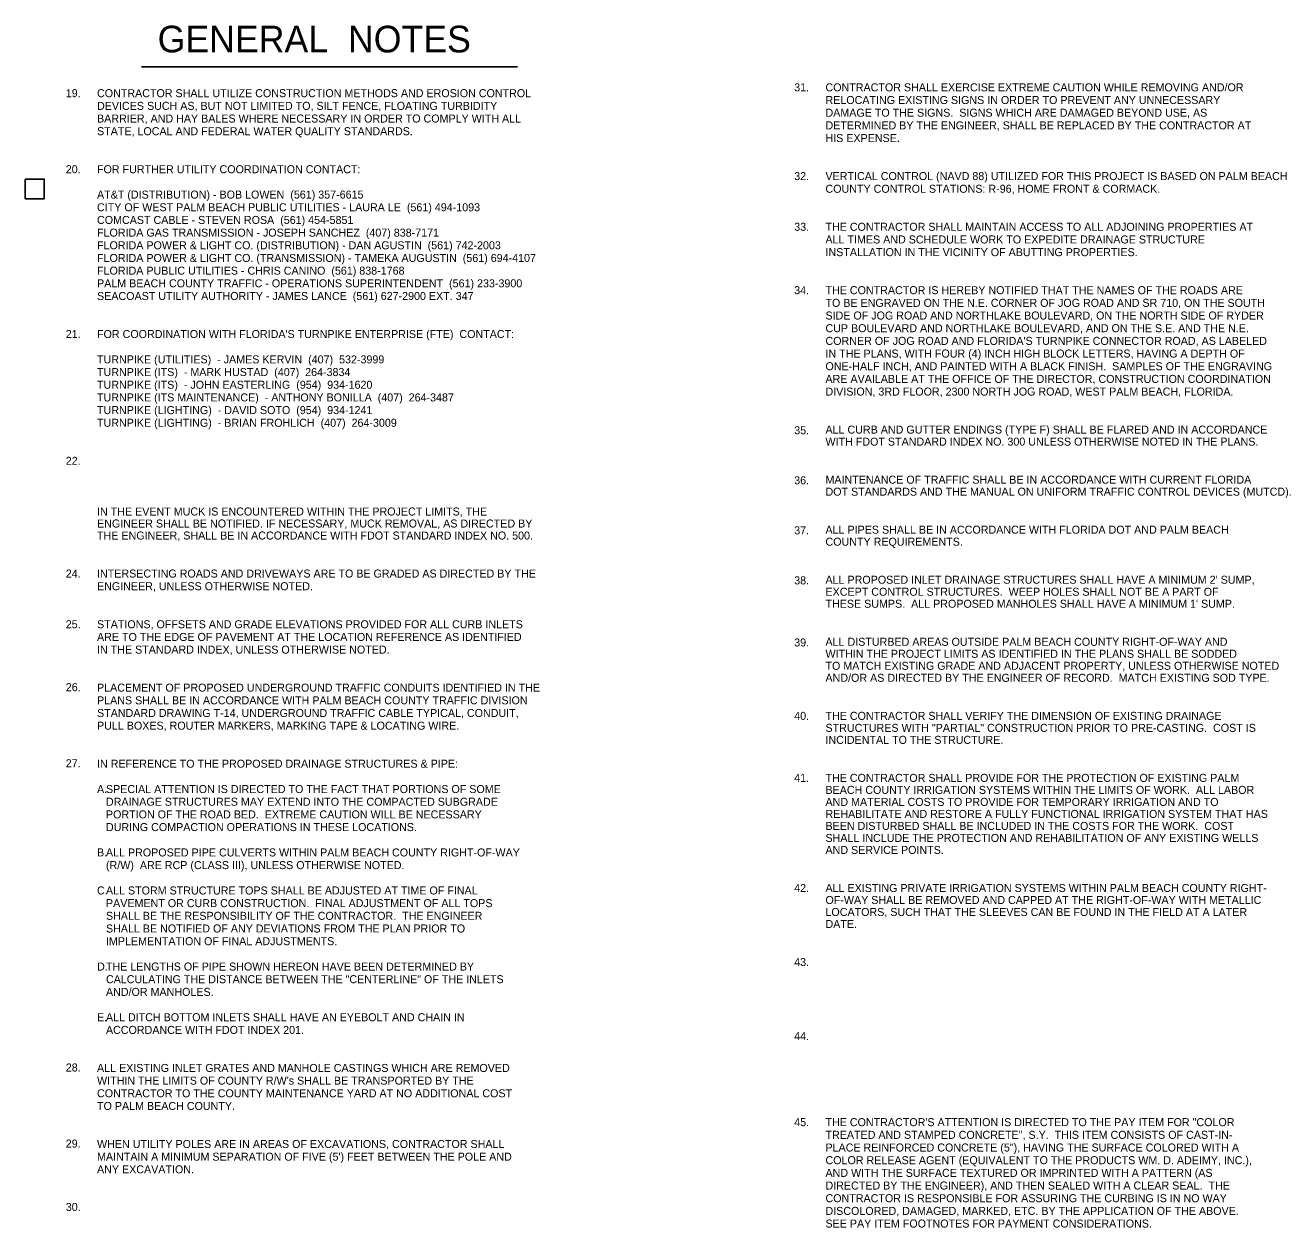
# Model space of a CAD drawing. Extents: x 783907 to 784590, y 832310 to 832609.
# Drawn here: x 784245.9 to 784340.8, y 832518.9 to 832609 of the extents above; entities that cross this region are included whole.
import ezdxf

# ---------------------------------------------------------------- set-up
doc = ezdxf.new("R2010")
doc.units = 0
doc.layers.add('Default', color=7, linetype='Continuous')

msp = doc.modelspace()

# ---------------------------------------------------------------- linework, layer by layer
at = {"layer": 'Default'}
msp.add_line((784254.603, 832605.859), (784282.795, 832605.859), dxfattribs=at)
msp.add_lwpolyline([(784245.898, 832597.448), (784247.319, 832597.448), (784247.319, 832595.971), (784245.898, 832595.971)], close=True, dxfattribs=at)

# ---------------------------------------------------------------- texts
for s, height, p in [('GENERAL  NOTES', 2, (784255.817, 832606.943)), ('31.', 0.6, (784303.539, 832604.024)), ('CONTRACTOR SHALL EXERCISE EXTREME CAUTION WHILE REMOVING AND/OR', 0.6, (784305.882, 832604.024)), ('19.', 0.6, (784248.932, 832603.587)), ('CONTRACTOR SHALL UTILIZE CONSTRUCTION METHODS AND EROSION CONTROL', 0.6, (784251.275, 832603.587)), ('RELOCATING EXISTING SIGNS IN ORDER TO PREVENT ANY UNNECESSARY', 0.6, (784305.882, 832603.074)), ('DEVICES SUCH AS, BUT NOT LIMITED TO, SILT FENCE, FLOATING TURBIDITY', 0.6, (784251.275, 832602.637)), ('DAMAGE TO THE SIGNS.  SIGNS WHICH ARE DAMAGED BEYOND USE, AS', 0.6, (784305.882, 832602.124)), ('BARRIER, AND HAY BALES WHERE NECESSARY IN ORDER TO COMPLY WITH ALL', 0.6, (784251.275, 832601.687)), ('DETERMINED BY THE ENGINEER, SHALL BE REPLACED BY THE CONTRACTOR AT', 0.6, (784305.882, 832601.174)), ('STATE, LOCAL AND FEDERAL WATER QUALITY STANDARDS.', 0.6, (784251.275, 832600.737)), ('HIS EXPENSE.', 0.6, (784305.882, 832600.224)), ('20.', 0.6, (784248.932, 832597.887)), ('FOR FURTHER UTILITY COORDINATION CONTACT:', 0.6, (784251.275, 832597.887)), ('32.', 0.6, (784303.539, 832597.374)), ('VERTICAL CONTROL (NAVD 88) UTILIZED FOR THIS PROJECT IS BASED ON PALM BEACH', 0.6, (784305.882, 832597.374)), ('COUNTY CONTROL STATIONS: R-96, HOME FRONT & CORMACK.', 0.6, (784305.882, 832596.424)), ('AT&T (DISTRIBUTION) - BOB LOWEN  (561) 357-6615 ', 0.6, (784251.275, 832595.987)), ('CITY OF WEST PALM BEACH PUBLIC UTILITIES - LAURA LE  (561) 494-1093 ', 0.6, (784251.275, 832595.037)), ('COMCAST CABLE - STEVEN ROSA  (561) 454-5851', 0.6, (784251.275, 832594.087)), ('33.', 0.6, (784303.539, 832593.574)), ('THE CONTRACTOR SHALL MAINTAIN ACCESS TO ALL ADJOINING PROPERTIES AT', 0.6, (784305.882, 832593.574)), ('FLORIDA GAS TRANSMISSION - JOSEPH SANCHEZ  (407) 838-7171', 0.6, (784251.275, 832593.137)), ('ALL TIMES AND SCHEDULE WORK TO EXPEDITE DRAINAGE STRUCTURE', 0.6, (784305.882, 832592.624)), ('FLORIDA POWER & LIGHT CO. (DISTRIBUTION) - DAN AGUSTIN  (561) 742-2003', 0.6, (784251.275, 832592.187)), ('INSTALLATION IN THE VICINITY OF ABUTTING PROPERTIES.', 0.6, (784305.882, 832591.674)), ('FLORIDA POWER & LIGHT CO. (TRANSMISSION) - TAMEKA AUGUSTIN  (561) 694-4107', 0.6, (784251.275, 832591.237)), ('FLORIDA PUBLIC UTILITIES - CHRIS CANINO  (561) 838-1768', 0.6, (784251.275, 832590.287)), ('PALM BEACH COUNTY TRAFFIC - OPERATIONS SUPERINTENDENT  (561) 233-3900', 0.6, (784251.275, 832589.337)), ('34.', 0.6, (784303.539, 832588.824)), ('THE CONTRACTOR IS HEREBY NOTIFIED THAT THE NAMES OF THE ROADS ARE', 0.6, (784305.882, 832588.824)), ('SEACOAST UTILITY AUTHORITY - JAMES LANCE  (561) 627-2900 EXT. 347', 0.6, (784251.275, 832588.387)), ('TO BE ENGRAVED ON THE N.E. CORNER OF JOG ROAD AND SR 710, ON THE SOUTH', 0.6, (784305.882, 832587.874)), ('SIDE OF JOG ROAD AND NORTHLAKE BOULEVARD, ON THE NORTH SIDE OF RYDER', 0.6, (784305.882, 832586.924)), ('CUP BOULEVARD AND NORTHLAKE BOULEVARD, AND ON THE S.E. AND THE N.E.', 0.6, (784305.882, 832585.974)), ('21.', 0.6, (784248.932, 832585.537)), ("FOR COORDINATION WITH FLORIDA'S TURNPIKE ENTERPRISE (FTE)  CONTACT:", 0.6, (784251.275, 832585.537)), ("CORNER OF JOG ROAD AND FLORIDA'S TURNPIKE CONNECTOR ROAD, AS LABELED", 0.6, (784305.882, 832585.024)), ('IN THE PLANS, WITH FOUR (4) INCH HIGH BLOCK LETTERS, HAVING A DEPTH OF', 0.6, (784305.882, 832584.074)), ('TURNPIKE (UTILITIES)  - JAMES KERVIN  (407)  532-3999', 0.6, (784251.275, 832583.637)), ('ONE-HALF INCH, AND PAINTED WITH A BLACK FINISH.  SAMPLES OF THE ENGRAVING', 0.6, (784305.882, 832583.124)), ('TURNPIKE (ITS)  - MARK HUSTAD  (407)  264-3834', 0.6, (784251.275, 832582.687)), ('ARE AVAILABLE AT THE OFFICE OF THE DIRECTOR, CONSTRUCTION COORDINATION', 0.6, (784305.882, 832582.174)), ('TURNPIKE (ITS)  - JOHN EASTERLING  (954)  934-1620', 0.6, (784251.275, 832581.737)), ('DIVISION, 3RD FLOOR, 2300 NORTH JOG ROAD, WEST PALM BEACH, FLORIDA. ', 0.6, (784305.882, 832581.224)), ('TURNPIKE (ITS MAINTENANCE)  - ANTHONY BONILLA  (407)  264-3487', 0.6, (784251.275, 832580.787)), ('TURNPIKE (LIGHTING)  - DAVID SOTO  (954)  934-1241', 0.6, (784251.275, 832579.837)), ('TURNPIKE (LIGHTING)  - BRIAN FROHLICH  (407)  264-3009', 0.6, (784251.275, 832578.887)), ('35.', 0.6, (784303.539, 832578.324)), ('ALL CURB AND GUTTER ENDINGS (TYPE F) SHALL BE FLARED AND IN ACCORDANCE', 0.6, (784305.882, 832578.374)), ('WITH FDOT STANDARD INDEX NO. 300 UNLESS OTHERWISE NOTED IN THE PLANS.', 0.6, (784305.882, 832577.474)), ('22.', 0.6, (784248.932, 832576.037)), ('36.', 0.6, (784303.539, 832574.574)), ('MAINTENANCE OF TRAFFIC SHALL BE IN ACCORDANCE WITH CURRENT FLORIDA ', 0.6, (784305.882, 832574.624)), ('DOT STANDARDS AND THE MANUAL ON UNIFORM TRAFFIC CONTROL DEVICES (MUTCD).', 0.6, (784305.882, 832573.724)), ('IN THE EVENT MUCK IS ENCOUNTERED WITHIN THE PROJECT LIMITS, THE', 0.6, (784251.275, 832572.237)), ('ENGINEER SHALL BE NOTIFIED. IF NECESSARY, MUCK REMOVAL, AS DIRECTED BY', 0.6, (784251.275, 832571.337)), ('37.', 0.6, (784303.539, 832570.824)), ('ALL PIPES SHALL BE IN ACCORDANCE WITH FLORIDA DOT AND PALM BEACH', 0.6, (784305.882, 832570.874)), ('THE ENGINEER, SHALL BE IN ACCORDANCE WITH FDOT STANDARD INDEX NO. 500. ', 0.6, (784251.275, 832570.437)), ('COUNTY REQUIREMENTS.', 0.6, (784305.882, 832569.974)), ('24.', 0.6, (784248.932, 832567.587)), ('INTERSECTING ROADS AND DRIVEWAYS ARE TO BE GRADED AS DIRECTED BY THE', 0.6, (784251.275, 832567.587)), ('38.', 0.6, (784303.539, 832567.074)), ("ALL PROPOSED INLET DRAINAGE STRUCTURES SHALL HAVE A MINIMUM 2' SUMP, ", 0.6, (784305.882, 832567.124)), ('ENGINEER, UNLESS OTHERWISE NOTED.', 0.6, (784251.275, 832566.637)), ('EXCEPT CONTROL STRUCTURES.  WEEP HOLES SHALL NOT BE A PART OF', 0.6, (784305.882, 832566.224)), ("THESE SUMPS.  ALL PROPOSED MANHOLES SHALL HAVE A MINIMUM 1' SUMP.", 0.6, (784305.882, 832565.324)), ('25.', 0.6, (784248.932, 832563.787)), ('STATIONS, OFFSETS AND GRADE ELEVATIONS PROVIDED FOR ALL CURB INLETS', 0.6, (784251.275, 832563.787)), ('ARE TO THE EDGE OF PAVEMENT AT THE LOCATION REFERENCE AS IDENTIFIED', 0.6, (784251.275, 832562.837)), ('39.', 0.6, (784303.539, 832562.424)), ('ALL DISTURBED AREAS OUTSIDE PALM BEACH COUNTY RIGHT-OF-WAY AND', 0.6, (784305.882, 832562.474)), ('IN THE STANDARD INDEX, UNLESS OTHERWISE NOTED.', 0.6, (784251.275, 832561.887)), ('WITHIN THE PROJECT LIMITS AS IDENTIFIED IN THE PLANS SHALL BE SODDED', 0.6, (784305.882, 832561.574)), ('TO MATCH EXISTING GRADE AND ADJACENT PROPERTY, UNLESS OTHERWISE NOTED', 0.6, (784305.882, 832560.674)), ('AND/OR AS DIRECTED BY THE ENGINEER OF RECORD.  MATCH EXISTING SOD TYPE.', 0.6, (784305.882, 832559.774)), ('26.', 0.6, (784248.932, 832559.069)), ('PLACEMENT OF PROPOSED UNDERGROUND TRAFFIC CONDUITS IDENTIFIED IN THE ', 0.6, (784251.275, 832559.037)), ('PLANS SHALL BE IN ACCORDANCE WITH PALM BEACH COUNTY TRAFFIC DIVISION', 0.6, (784251.275, 832558.087)), ('STANDARD DRAWING T-14, UNDERGROUND TRAFFIC CABLE TYPICAL, CONDUIT, ', 0.6, (784251.275, 832557.137)), ('40.', 0.6, (784303.539, 832556.924)), ('THE CONTRACTOR SHALL VERIFY THE DIMENSION OF EXISTING DRAINAGE', 0.6, (784305.882, 832556.924)), ('PULL BOXES, ROUTER MARKERS, MARKING TAPE & LOCATING WIRE.', 0.6, (784251.275, 832556.187)), ('STRUCTURES WITH "PARTIAL" CONSTRUCTION PRIOR TO PRE-CASTING.  COST IS', 0.6, (784305.882, 832556.024)), ('INCIDENTAL TO THE STRUCTURE.', 0.6, (784305.882, 832555.124)), ('27.', 0.6, (784248.932, 832553.369)), ('IN REFERENCE TO THE PROPOSED DRAINAGE STRUCTURES & PIPE:', 0.6, (784251.275, 832553.337)), ('41.', 0.6, (784303.539, 832552.274)), ('THE CONTRACTOR SHALL PROVIDE FOR THE PROTECTION OF EXISTING PALM', 0.6, (784305.882, 832552.274)), ('A.', 0.6, (784251.275, 832551.437)), ('   SPECIAL ATTENTION IS DIRECTED TO THE FACT THAT PORTIONS OF SOME', 0.6, (784251.275, 832551.437)), ('BEACH COUNTY IRRIGATION SYSTEMS WITHIN THE LIMITS OF WORK.  ALL LABOR', 0.6, (784305.882, 832551.374)), ('   DRAINAGE STRUCTURES MAY EXTEND INTO THE COMPACTED SUBGRADE', 0.6, (784251.275, 832550.487)), ('AND MATERIAL COSTS TO PROVIDE FOR TEMPORARY IRRIGATION AND TO', 0.6, (784305.882, 832550.474)), ('   PORTION OF THE ROAD BED.  EXTREME CAUTION WILL BE NECESSARY', 0.6, (784251.275, 832549.537)), ('REHABILITATE AND RESTORE A FULLY FUNCTIONAL IRRIGATION SYSTEM THAT HAS', 0.6, (784305.882, 832549.574)), ('   DURING COMPACTION OPERATIONS IN THESE LOCATIONS.', 0.6, (784251.275, 832548.587)), ('BEEN DISTURBED SHALL BE INCLUDED IN THE COSTS FOR THE WORK.  COST', 0.6, (784305.882, 832548.674)), ('SHALL INCLUDE THE PROTECTION AND REHABILITATION OF ANY EXISTING WELLS', 0.6, (784305.882, 832547.774)), ('B.', 0.6, (784251.275, 832546.687)), ('   ALL PROPOSED PIPE CULVERTS WITHIN PALM BEACH COUNTY RIGHT-OF-WAY', 0.6, (784251.275, 832546.687)), ('AND SERVICE POINTS.', 0.6, (784305.882, 832546.874)), ('   (R/W)  ARE RCP (CLASS III), UNLESS OTHERWISE NOTED.', 0.6, (784251.275, 832545.737)), ('C.', 0.6, (784251.275, 832543.837)), ('   ALL STORM STRUCTURE TOPS SHALL BE ADJUSTED AT TIME OF FINAL', 0.6, (784251.275, 832543.837)), ('42.', 0.6, (784303.539, 832544.024)), ('ALL EXISTING PRIVATE IRRIGATION SYSTEMS WITHIN PALM BEACH COUNTY RIGHT-', 0.6, (784305.882, 832544.024)), ('   PAVEMENT OR CURB CONSTRUCTION.  FINAL ADJUSTMENT OF ALL TOPS', 0.6, (784251.275, 832542.887)), ('OF-WAY SHALL BE REMOVED AND CAPPED AT THE RIGHT-OF-WAY WITH METALLIC', 0.6, (784305.882, 832543.124)), ('LOCATORS, SUCH THAT THE SLEEVES CAN BE FOUND IN THE FIELD AT A LATER', 0.6, (784305.882, 832542.224)), ('   SHALL BE THE RESPONSIBILITY OF THE CONTRACTOR.  THE ENGINEER', 0.6, (784251.275, 832541.937)), ('DATE.', 0.6, (784305.882, 832541.324)), ('   SHALL BE NOTIFIED OF ANY DEVIATIONS FROM THE PLAN PRIOR TO ', 0.6, (784251.275, 832540.987)), ('   IMPLEMENTATION OF FINAL ADJUSTMENTS.', 0.6, (784251.275, 832540.037)), ('43.', 0.6, (784303.539, 832538.474)), ('D.', 0.6, (784251.275, 832538.137)), ('   THE LENGTHS OF PIPE SHOWN HEREON HAVE BEEN DETERMINED BY', 0.6, (784251.275, 832538.137)), ('   CALCULATING THE DISTANCE BETWEEN THE "CENTERLINE" OF THE INLETS', 0.6, (784251.275, 832537.187)), ('   AND/OR MANHOLES.', 0.6, (784251.275, 832536.237)), ('E.', 0.6, (784251.275, 832534.337)), ('   ALL DITCH BOTTOM INLETS SHALL HAVE AN EYEBOLT AND CHAIN IN', 0.6, (784251.275, 832534.337)), ('   ACCORDANCE WITH FDOT INDEX 201.', 0.6, (784251.275, 832533.387)), ('44.', 0.6, (784303.539, 832532.924)), ('28.', 0.6, (784248.932, 832530.57)), ('ALL EXISTING INLET GRATES AND MANHOLE CASTINGS WHICH ARE REMOVED', 0.6, (784251.275, 832530.537)), ("WITHIN THE LIMITS OF COUNTY R/W's SHALL BE TRANSPORTED BY THE", 0.6, (784251.275, 832529.587)), ('CONTRACTOR TO THE COUNTY MAINTENANCE YARD AT NO ADDITIONAL COST', 0.6, (784251.275, 832528.637)), ('TO PALM BEACH COUNTY.', 0.6, (784251.275, 832527.687)), ('45.', 0.6, (784303.539, 832526.474)), ('THE CONTRACTOR\'S ATTENTION IS DIRECTED TO THE PAY ITEM FOR "COLOR ', 0.6, (784305.882, 832526.474)), ('TREATED AND STAMPED CONCRETE", S.Y.  THIS ITEM CONSISTS OF CAST-IN-', 0.6, (784305.882, 832525.524)), ('29.', 0.6, (784248.932, 832524.87)), ('WHEN UTILITY POLES ARE IN AREAS OF EXCAVATIONS, CONTRACTOR SHALL', 0.6, (784251.275, 832524.837)), ('PLACE REINFORCED CONCRETE (5"), HAVING THE SURFACE COLORED WITH A', 0.6, (784305.882, 832524.574)), ("MAINTAIN A MINIMUM SEPARATION OF FIVE (5') FEET BETWEEN THE POLE AND", 0.6, (784251.275, 832523.887)), ('COLOR RELEASE AGENT (EQUIVALENT TO THE PRODUCTS WM. D. ADEIMY, INC.), ', 0.6, (784305.882, 832523.624)), ('ANY EXCAVATION.', 0.6, (784251.275, 832522.937)), ('AND WITH THE SURFACE TEXTURED OR IMPRINTED WITH A PATTERN (AS ', 0.6, (784305.882, 832522.674)), ('DIRECTED BY THE ENGINEER), AND THEN SEALED WITH A CLEAR SEAL.  THE ', 0.6, (784305.882, 832521.724)), ('CONTRACTOR IS RESPONSIBLE FOR ASSURING THE CURBING IS IN NO WAY ', 0.6, (784305.882, 832520.774)), ('30.', 0.6, (784248.932, 832520.12)), ('DISCOLORED, DAMAGED, MARKED, ETC. BY THE APPLICATION OF THE ABOVE.  ', 0.6, (784305.882, 832519.824)), ('SEE PAY ITEM FOOTNOTES FOR PAYMENT CONSIDERATIONS.', 0.6, (784305.882, 832518.874))]:
    msp.add_text(s, height=height, dxfattribs=at).set_placement(p)

doc.saveas('drawing.dxf')
